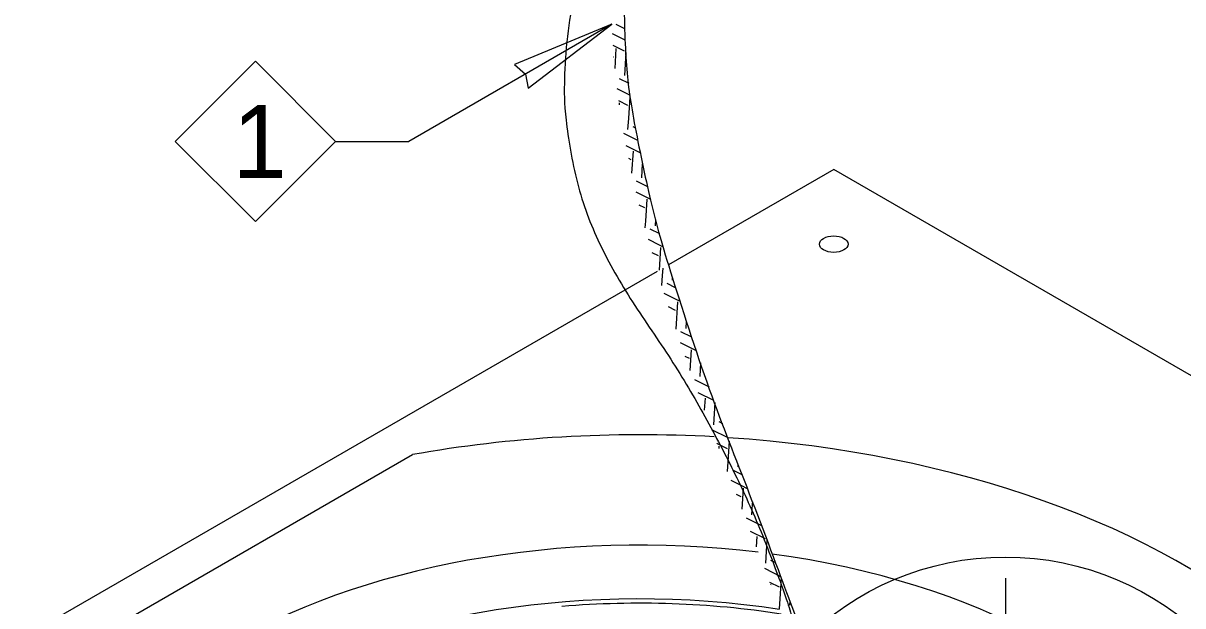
# Model space of a CAD drawing. Extents: x 99862 to 103151, y 100000 to 105076.
# Drawn here: x 100651.8 to 100905.5, y 104736.7 to 104864.2 of the extents above; entities that cross this region are included whole.
import ezdxf

# ---------------------------------------------------------------- set-up
doc = ezdxf.new("R2010")
doc.units = 0
for name, color, linetype in [('Level 10', 7, 'Continuous'), ('Level 11', 7, 'Continuous'), ('Level 15', 7, 'Continuous'), ('Level 16', 7, 'Continuous'), ('Level 18', 7, 'Continuous'), ('Level 20', 7, 'Continuous')]:
    doc.layers.add(name, color=color, linetype=linetype)

msp = doc.modelspace()

# ---------------------------------------------------------------- linework, layer by layer
at = {"layer": 'Level 10'}
for p, q in [((100829.13, 104832.19), (100792.95, 104811.31)), ((101055.4, 104701.55), (100829.13, 104832.19)), ((100790.52, 104809.9), (100518, 104652.56))]:
    msp.add_line(p, q, dxfattribs=at)
msp.add_ellipse((100829.13, 104815.86), major_axis=(3.12, 0), ratio=0.57735, dxfattribs=at)
at = {"layer": 'Level 11'}
msp.add_line((100626.11, 104705.8), (100736.92, 104769.77), dxfattribs=at)
for centre, major_axis, start_param, end_param in [((100786.7, 104677.06), (-168.12, 0), 4.615397, 5.012966), ((100786.7, 104677.06), (-168.12, 0), 2.841016, 4.597524), ((100786.7, 104677.06), (-126.25, 0), 4.505668, 6.544985), ((100786.7, 104677.06), (-126.25, 0), 2.356194, 4.480754), ((100786.7, 104668.89), (120, 0), 1.313331, 3.403392), ((100786.7, 104668.89), (-118.37, 0), 4.448074, 4.856839)]:
    msp.add_ellipse(centre, major_axis=major_axis, ratio=0.57735, start_param=start_param, end_param=end_param, dxfattribs=at)
at = {"layer": 'Level 15'}
for p, q in [((100780.56, 104864), (100736.13, 104838.35)), ((100720.13, 104838.35), (100736.13, 104838.35)), ((100866.7, 104742.74), (100866.7, 104715.29))]:
    msp.add_line(p, q, dxfattribs=at)
msp.add_lwpolyline([(100780.56, 104864), (100759.3, 104855.17), (100761.7, 104853.11), (100762.28, 104850)], close=True, dxfattribs=at)
msp.add_circle((100866.7, 104684.82), 62.53, dxfattribs=at)
at = {"layer": 'Level 16'}
for p, q in [((100781.45, 104864.03), (100783.32, 104863.1)), ((100780.64, 104861.96), (100783.44, 104860.57)), ((100780.77, 104859.43), (100783.29, 104858.18)), ((100781.47, 104858.67), (100781.19, 104854.33)), ((100783.44, 104860.57), (100783.44, 104860.57)), ((100780.95, 104856.87), (100780.98, 104856.85)), ((100783.63, 104857.8), (100783.31, 104852.82)), ((100782.16, 104852.16), (100784.28, 104851.11)), ((100781.66, 104849.93), (100784.61, 104848.47)), ((100784.49, 104848.12), (100784.18, 104843.34)), ((100782.02, 104847.29), (100784, 104846.31)), ((100782.18, 104846.79), (100782.15, 104846.36)), ((100784.18, 104843.34), (100784.02, 104840.95)), ((100785.17, 104841.61), (100785.71, 104841.34)), ((100783.15, 104840.14), (100786.21, 104838.63)), ((100783.65, 104837.43), (100786.73, 104835.9)), ((100785.2, 104836.25), (100784.89, 104831.42)), ((100784.18, 104834.69), (100784.71, 104834.43)), ((100787.24, 104833.47), (100787.04, 104830.4)), ((100785.89, 104829.74), (100788.34, 104828.52)), ((100785.81, 104827.3), (100789.02, 104825.72)), ((100788.21, 104825.71), (100787.91, 104820.92)), ((100786.51, 104824.49), (100787.73, 104823.89)), ((100787.91, 104820.92), (100787.81, 104819.41)), ((100790.15, 104821.27), (100790.06, 104819.86)), ((100788.9, 104819.19), (100790.98, 104818.16)), ((100788.49, 104816.93), (100790.9, 104815.74)), ((100790.9, 104815.74), (100791.79, 104815.3)), ((100791.23, 104815.16), (100790.91, 104810.13)), ((100789.29, 104814.06), (100790.74, 104813.34)), ((100791.71, 104810.59), (100791.61, 104809.02)), ((100791.61, 104809.02), (100791.46, 104806.78)), ((100793.79, 104808.52), (100793.76, 104807.95)), ((100791.98, 104805.13), (100794.6, 104803.83)), ((100792.6, 104807.29), (100794.46, 104806.37)), ((100794.93, 104803.26), (100794.54, 104797.23)), ((100794.6, 104803.83), (100795.39, 104803.45)), ((100792.92, 104802.2), (100794.45, 104801.44)), ((100796.87, 104798.9), (100796.77, 104797.41)), ((100795.62, 104796.74), (100797.99, 104795.57)), ((100795.54, 104794.32), (100799.01, 104792.6)), ((100797.95, 104792.71), (100797.66, 104788.21)), ((100796.56, 104791.34), (100797.46, 104790.9)), ((100799.98, 104789.85), (100799.79, 104786.87)), ((100798.64, 104786.2), (100801.85, 104784.61)), ((100799.4, 104783.36), (100802.78, 104781.68)), ((100800.96, 104782.17), (100800.8, 104779.54)), ((100803.12, 104781.15), (100802.81, 104776.32)), ((100803.96, 104776.99), (100804.81, 104776.56)), ((100802.37, 104775.3), (100805.95, 104773.53)), ((100803.51, 104772.27), (100803.65, 104772.2)), ((100803.65, 104772.2), (100805.8, 104771.14)), ((100806.27, 104772.69), (100805.98, 104768.17)), ((100803.98, 104771.62), (100803.95, 104771.1)), ((100805.98, 104768.17), (100805.84, 104766.11)), ((100808.16, 104767.69), (100808.13, 104767.11)), ((100806.59, 104764.16), (100808.97, 104762.99)), ((100806.97, 104766.44), (100809.03, 104765.42)), ((100808.97, 104762.99), (100810.19, 104762.38)), ((100809.3, 104762.41), (100809.01, 104757.84)), ((100807.75, 104761.12), (100808.81, 104760.59)), ((100811.33, 104759.42), (100811.3, 104758.95)), ((100811.3, 104758.95), (100811.14, 104756.56)), ((100809.99, 104755.9), (100813.31, 104754.26)), ((100810.86, 104753), (100814.13, 104751.38)), ((100812.32, 104751.87), (100812.17, 104749.57)), ((100814.49, 104751.15), (100814.16, 104746.02)), ((100815.31, 104746.68), (100816.38, 104746.15)), ((100813.94, 104744.89), (100817.51, 104743.12)), ((100815.07, 104741.86), (100817.15, 104740.83)), ((100815.33, 104741.32), (100815.32, 104741.17)), ((100817.64, 104742.65), (100817.21, 104736.03)), ((100819.53, 104737.63), (100819.48, 104736.8))]:
    msp.add_line(p, q, dxfattribs=at)
at = {"layer": 'Level 18'}
for points, degree in [([(100795.26, 104921.09), (100750.19, 104853.46), (100822.12, 104749.9), (100827.89, 104696.64)], 2), ([(100797.6, 104919.68), (100792.08, 104911.39), (100788.4, 104902.68), (100783.87, 104884.42), (100783.02, 104874.87), (100783.5, 104855.22), (100784.84, 104845.13), (100789.02, 104824.76), (100791.86, 104814.49), (100801.6, 104783.94), (100809.71, 104763.93), (100820.01, 104736.48), (100823.14, 104727.75), (100827.95, 104711.8), (100829.69, 104704.54), (100830.63, 104697.88)], 3)]:
    msp.add_open_spline(points, degree=degree, dxfattribs=at)
at = {"layer": 'Level 20'}
msp.add_lwpolyline([(100702.58, 104820.79), (100720.13, 104838.35), (100702.58, 104855.9), (100685.03, 104838.35)], close=True, dxfattribs=at)

# ---------------------------------------------------------------- texts
msp.add_text('1', height=16, dxfattribs=at).set_placement((100697.55, 104830.34))

doc.saveas('drawing.dxf')
